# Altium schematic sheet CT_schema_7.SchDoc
size 274 x 160 mm
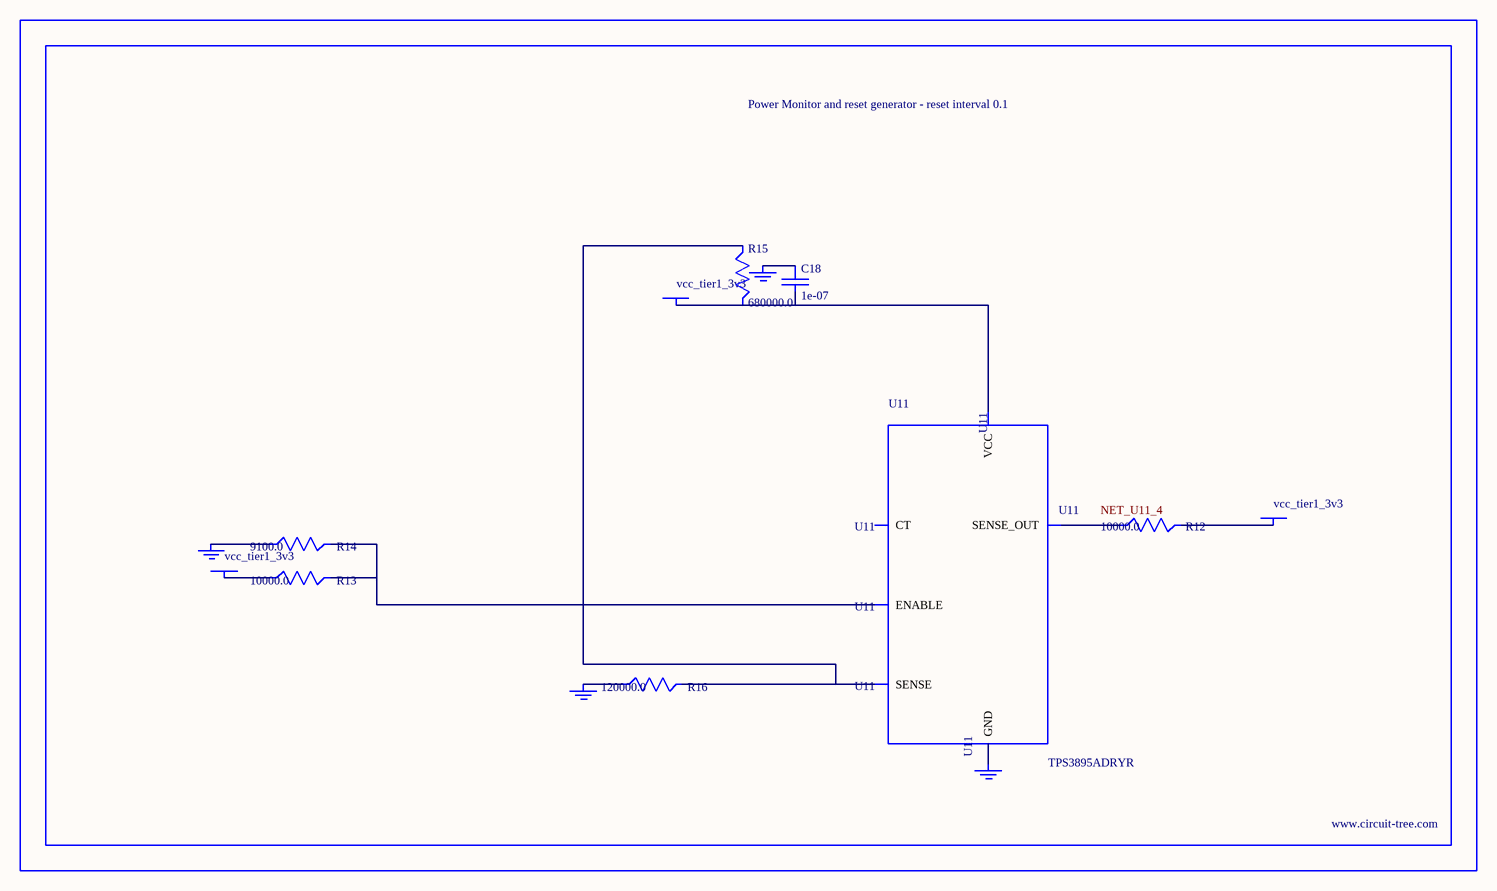
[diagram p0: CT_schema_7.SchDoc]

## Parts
BORDER6  (no value)
C18  1e-07  [C0402]
GND_INSTANCE_6_0  (no value)
GND_INSTANCE_6_1  (no value)
GND_INSTANCE_6_2  (no value)
GND_INSTANCE_6_3  (no value)
POWER_INSTANCE_6_0  vcc_tier1_3v3
POWER_INSTANCE_6_1  vcc_tier1_3v3
POWER_INSTANCE_6_2  vcc_tier1_3v3
R12  10000.0  [R0603]
R13  10000.0  [R0603]
R14  9100.0  [R0603]
R15  680000.0  [R0603]
R16  120000.0  [R0603]
U11  TPS3895ADRYR  [SON-6]

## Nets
NetC18_1: C18.1 GND_INSTANCE_6_2.0(GND)
NetC18_2: C18.2 POWER_INSTANCE_6_2.0(PWR) R15.2 U11.6(VCC)
NetGND_INSTANCE_6_0_0: GND_INSTANCE_6_0.0(GND) R14.1
NetGND_INSTANCE_6_1_0: GND_INSTANCE_6_1.0(GND) R16.1
NetGND_INSTANCE_6_3_0: GND_INSTANCE_6_3.0(GND) U11.2(GND)
NetPOWER_INSTANCE_6_0_0: POWER_INSTANCE_6_0.0(PWR) R13.1
NetPOWER_INSTANCE_6_1_0: POWER_INSTANCE_6_1.0(PWR) R12.2
NetR12_1: R12.1 U11.4(SENSE_OUT)
NetR13_2: R13.2 R14.2 U11.1(ENABLE)
NetR15_1: R15.1 R16.2 U11.3(SENSE)

Not connected (* = marked no-connect by the designer): U11 5(CT)

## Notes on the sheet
- Labels drawn without touching a wire or pin: NET_U11_4

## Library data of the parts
BORDER6 = BORDER_PAGE6
C18 = C0402C104K3RACTU
GND_INSTANCE_6_0-GND_INSTANCE_6_3 = GND
POWER_INSTANCE_6_0-POWER_INSTANCE_6_2 = PWR
R12 R13 = RC0603JR-0710KL
R14 = RC0603JR-079K1L
R15 = RC0603JR-07680KL
R16 = RC0603JR-07120KL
